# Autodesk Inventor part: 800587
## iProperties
Created: 2007-10
Part Number: 800587
Document SubType Name: Modeling
Designer: RS
Density: 1.13 g/cm^3
Mass: 0.132415 g
Surface Area: 5.13448 cm^2
Volume: 0.117182 cm^3
Material: Nylon-6/6
Description: SPLIT BUSHING 8 MM
Component Category: Fasteners
Author: RS
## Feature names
1. Revolution1
2. Extrusion1
